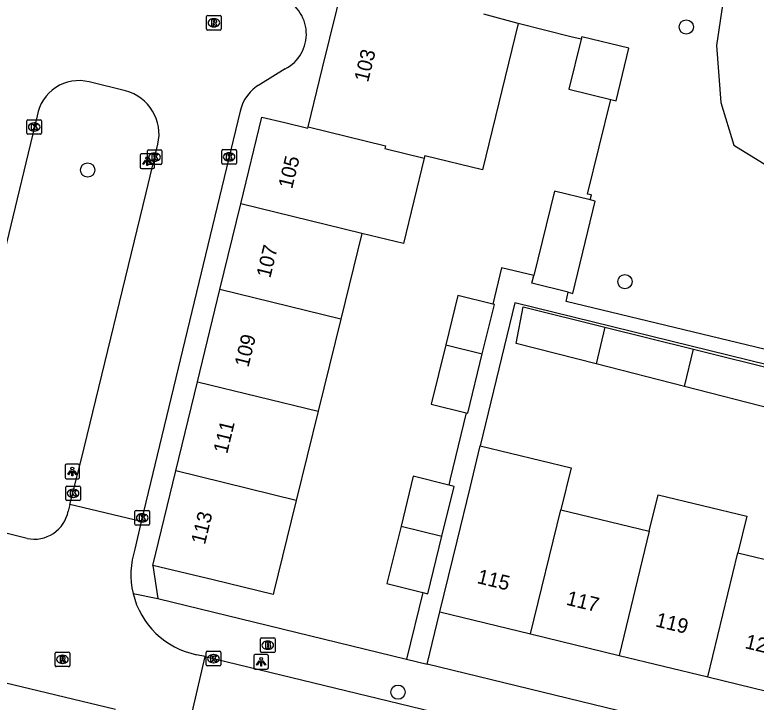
# Model space of a CAD drawing. Extents: x 162812 to 163818, y 381639 to 382470.
# Drawn here: x 163426.1 to 163477, y 382298.5 to 382345.6 of the extents above; entities that cross this region are included whole.
import ezdxf

# ---------------------------------------------------------------- set-up
doc = ezdxf.new("R2010")
doc.units = 0
for name, color, linetype in [('IMGEO_Boom', 7, 'Continuous'), ('IMGEO_Brandkraan', 7, 'Continuous'), ('IMGEO_Kolk', 7, 'Continuous'), ('IMGEO_Lichtpunt', 7, 'Continuous'), ('IMGEO_Loofbos', 7, 'Continuous'), ('IMGEO_Pand', 7, 'Continuous'), ('IMGEO_Pand_nummerreeks', 7, 'Continuous'), ('IMGEO_Rijbaan_lokaal_open', 7, 'Continuous'), ('IMGEO_Rioolput', 7, 'Continuous'), ('IMGEO_Voetpad_open', 7, 'Continuous')]:
    doc.layers.add(name, color=color, linetype=linetype)

msp = doc.modelspace()

# ---------------------------------------------------------------- linework, layer by layer
at = {"layer": 'IMGEO_Boom'}
for centre in [(163472.217, 382344.801), (163431.118, 382334.985), (163468.006, 382327.325), (163452.428, 382299.152)]:
    msp.add_circle(centre, 0.489, dxfattribs=at)
at = {"layer": 'IMGEO_Brandkraan'}
for p, q in [((163442.983, 382301.951), (163442.983, 382302.803)), ((163443.058, 382302.877), (163443.91, 382302.877)), ((163443.471, 382302.657), (163443.496, 382302.657)), ((163443.984, 382302.803), (163443.984, 382301.951)), ((163443.91, 382301.877), (163443.058, 382301.877)), ((163443.494, 382302.097), (163443.469, 382302.097))]:
    msp.add_line(p, q, dxfattribs=at)
for points in [[(163442.983, 382301.951), (163442.983, 382302.803)], [(163443.058, 382302.877), (163443.91, 382302.877)], [(163443.331, 382302.577), (163443.331, 382302.177), (163443.544, 382302.177)], [(163443.562, 382302.577), (163443.331, 382302.577)], [(163443.51, 382302.496), (163443.456, 382302.496), (163443.456, 382302.42)], [(163443.456, 382302.42), (163443.509, 382302.42)], [(163443.984, 382302.803), (163443.984, 382301.951)], [(163443.91, 382301.877), (163443.058, 382301.877)], [(163443.518, 382302.344), (163443.456, 382302.344), (163443.456, 382302.263)], [(163443.456, 382302.263), (163443.518, 382302.263)]]:
    msp.add_lwpolyline(points, dxfattribs=at)
for centre, radius, start, end in [((163443.06, 382302.801), 0.0765, 91.552, 178.448), ((163443.06, 382302.801), 0.0765, 91.552, 178.448), ((163443.511, 382302.458), 0.0379, 267.8285, 90.9355), ((163443.566, 382302.432), 0.145, 59.4692, 91.5367), ((163443.591, 382302.479), 0.0922, 285.5137, 58.1501), ((163443.596, 382302.287), 0.105, 301.3115, 78.989), ((163443.908, 382302.801), 0.0765, 1.552, 88.448), ((163443.908, 382302.801), 0.0765, 1.552, 88.448), ((163443.06, 382301.953), 0.0765, 181.552, 268.448), ((163443.06, 382301.953), 0.0765, 181.552, 268.448), ((163443.519, 382302.303), 0.0404, 269.8759, 90.5077), ((163443.55, 382302.428), 0.251, 268.6676, 293.5347), ((163443.908, 382301.953), 0.0765, 271.552, 358.448), ((163443.908, 382301.953), 0.0765, 271.552, 358.448)]:
    msp.add_arc(centre, radius, start, end, dxfattribs=at)
for centre, major_axis, ratio, start_param, end_param in [((163443.47, 382302.377), (-0.387, 0.002), 0.722429, 4.712389, 7.853982), ((163443.495, 382302.377), (-0.39, 0.002), 0.717154, 1.570796, 4.712389)]:
    msp.add_ellipse(centre, major_axis=major_axis, ratio=ratio, start_param=start_param, end_param=end_param, dxfattribs=at)
at = {"layer": 'IMGEO_Kolk'}
for p, q in [((163426.948, 382337.512), (163426.948, 382338.364)), ((163427.023, 382338.438), (163427.875, 382338.438)), ((163427.436, 382338.218), (163427.461, 382338.218)), ((163427.949, 382338.364), (163427.949, 382337.512)), ((163427.459, 382337.658), (163427.434, 382337.658)), ((163427.875, 382337.438), (163427.023, 382337.438)), ((163435.217, 382335.445), (163435.217, 382336.297)), ((163435.292, 382336.371), (163436.144, 382336.371)), ((163435.705, 382336.151), (163435.73, 382336.151)), ((163436.218, 382336.297), (163436.218, 382335.445)), ((163440.329, 382335.46), (163440.329, 382336.312)), ((163440.404, 382336.386), (163441.256, 382336.386)), ((163440.817, 382336.166), (163440.842, 382336.166)), ((163441.33, 382336.312), (163441.33, 382335.46)), ((163435.728, 382335.591), (163435.703, 382335.591)), ((163440.84, 382335.606), (163440.815, 382335.606)), ((163436.144, 382335.371), (163435.292, 382335.371)), ((163441.256, 382335.386), (163440.404, 382335.386)), ((163429.621, 382312.371), (163429.621, 382313.223)), ((163429.696, 382313.297), (163430.548, 382313.297)), ((163430.109, 382313.077), (163430.134, 382313.077)), ((163430.622, 382313.223), (163430.622, 382312.371)), ((163430.548, 382312.297), (163429.696, 382312.297)), ((163430.132, 382312.517), (163430.107, 382312.517)), ((163434.369, 382310.689), (163434.369, 382311.541)), ((163434.444, 382311.615), (163435.296, 382311.615)), ((163435.37, 382311.541), (163435.37, 382310.689)), ((163434.857, 382311.395), (163434.882, 382311.395)), ((163435.296, 382310.615), (163434.444, 382310.615)), ((163434.88, 382310.835), (163434.855, 382310.835)), ((163439.253, 382301.029), (163439.253, 382301.881)), ((163439.328, 382301.955), (163440.18, 382301.955)), ((163440.254, 382301.881), (163440.254, 382301.029)), ((163439.741, 382301.735), (163439.766, 382301.735)), ((163440.18, 382300.955), (163439.328, 382300.955)), ((163439.764, 382301.175), (163439.739, 382301.175))]:
    msp.add_line(p, q, dxfattribs=at)
for points in [[(163426.948, 382337.512), (163426.948, 382338.364)], [(163427.023, 382338.438), (163427.875, 382338.438)], [(163427.269, 382338.138), (163427.392, 382338.138), (163427.392, 382337.987), (163427.522, 382338.138), (163427.686, 382338.138), (163427.54, 382337.987), (163427.693, 382337.738), (163427.541, 382337.738), (163427.456, 382337.902), (163427.392, 382337.835), (163427.392, 382337.738), (163427.269, 382337.738), (163427.269, 382338.138)], [(163427.949, 382338.364), (163427.949, 382337.512)], [(163427.875, 382337.438), (163427.023, 382337.438)], [(163435.217, 382335.445), (163435.217, 382336.297)], [(163435.292, 382336.371), (163436.144, 382336.371)], [(163435.538, 382336.071), (163435.661, 382336.071), (163435.661, 382335.92), (163435.791, 382336.071), (163435.955, 382336.071), (163435.809, 382335.92), (163435.962, 382335.671), (163435.81, 382335.671), (163435.725, 382335.835), (163435.661, 382335.768), (163435.661, 382335.671), (163435.538, 382335.671), (163435.538, 382336.071)], [(163436.218, 382336.297), (163436.218, 382335.445)], [(163440.329, 382335.46), (163440.329, 382336.312)], [(163440.404, 382336.386), (163441.256, 382336.386)], [(163440.65, 382336.086), (163440.773, 382336.086), (163440.773, 382335.935), (163440.903, 382336.086), (163441.067, 382336.086), (163440.921, 382335.935), (163441.074, 382335.686), (163440.922, 382335.686), (163440.837, 382335.85), (163440.773, 382335.783), (163440.773, 382335.686), (163440.65, 382335.686), (163440.65, 382336.086)], [(163441.33, 382336.312), (163441.33, 382335.46)], [(163436.144, 382335.371), (163435.292, 382335.371)], [(163441.256, 382335.386), (163440.404, 382335.386)], [(163429.621, 382312.371), (163429.621, 382313.223)], [(163429.696, 382313.297), (163430.548, 382313.297)], [(163430.622, 382313.223), (163430.622, 382312.371)], [(163429.942, 382312.997), (163430.065, 382312.997), (163430.065, 382312.846), (163430.195, 382312.997), (163430.359, 382312.997), (163430.213, 382312.846), (163430.366, 382312.597), (163430.214, 382312.597), (163430.129, 382312.761), (163430.065, 382312.694), (163430.065, 382312.597), (163429.942, 382312.597), (163429.942, 382312.997)], [(163430.548, 382312.297), (163429.696, 382312.297)], [(163434.369, 382310.689), (163434.369, 382311.541)], [(163434.444, 382311.615), (163435.296, 382311.615)], [(163435.37, 382311.541), (163435.37, 382310.689)], [(163434.69, 382311.315), (163434.813, 382311.315), (163434.813, 382311.164), (163434.943, 382311.315), (163435.107, 382311.315), (163434.961, 382311.164), (163435.114, 382310.915), (163434.962, 382310.915), (163434.877, 382311.079), (163434.813, 382311.012), (163434.813, 382310.915), (163434.69, 382310.915), (163434.69, 382311.315)], [(163435.296, 382310.615), (163434.444, 382310.615)], [(163439.253, 382301.029), (163439.253, 382301.881)], [(163439.328, 382301.955), (163440.18, 382301.955)], [(163440.254, 382301.881), (163440.254, 382301.029)], [(163439.574, 382301.655), (163439.697, 382301.655), (163439.697, 382301.504), (163439.827, 382301.655), (163439.991, 382301.655), (163439.845, 382301.504), (163439.998, 382301.255), (163439.846, 382301.255), (163439.761, 382301.419), (163439.697, 382301.352), (163439.697, 382301.255), (163439.574, 382301.255), (163439.574, 382301.655)], [(163440.18, 382300.955), (163439.328, 382300.955)]]:
    msp.add_lwpolyline(points, dxfattribs=at)
for centre, start, end in [((163427.025, 382338.362), 91.552, 178.448), ((163427.025, 382338.362), 91.552, 178.448), ((163427.873, 382338.362), 1.552, 88.448), ((163427.873, 382338.362), 1.552, 88.448), ((163427.025, 382337.514), 181.552, 268.448), ((163427.025, 382337.514), 181.552, 268.448), ((163427.873, 382337.514), 271.552, 358.448), ((163427.873, 382337.514), 271.552, 358.448), ((163435.294, 382336.295), 91.552, 178.448), ((163435.294, 382336.295), 91.552, 178.448), ((163436.142, 382336.295), 1.552, 88.448), ((163436.142, 382336.295), 1.552, 88.448), ((163440.406, 382336.31), 91.552, 178.448), ((163440.406, 382336.31), 91.552, 178.448), ((163441.254, 382336.31), 1.552, 88.448), ((163441.254, 382336.31), 1.552, 88.448), ((163440.406, 382335.462), 181.552, 268.448), ((163440.406, 382335.462), 181.552, 268.448), ((163441.254, 382335.462), 271.552, 358.448), ((163441.254, 382335.462), 271.552, 358.448), ((163435.294, 382335.447), 181.552, 268.448), ((163435.294, 382335.447), 181.552, 268.448), ((163436.142, 382335.447), 271.552, 358.448), ((163436.142, 382335.447), 271.552, 358.448), ((163429.698, 382313.221), 91.552, 178.448), ((163429.698, 382313.221), 91.552, 178.448), ((163430.546, 382313.221), 1.552, 88.448), ((163430.546, 382313.221), 1.552, 88.448), ((163429.698, 382312.373), 181.552, 268.448), ((163429.698, 382312.373), 181.552, 268.448), ((163430.546, 382312.373), 271.552, 358.448), ((163430.546, 382312.373), 271.552, 358.448), ((163434.446, 382311.539), 91.552, 178.448), ((163434.446, 382311.539), 91.552, 178.448), ((163435.294, 382311.539), 1.552, 88.448), ((163435.294, 382311.539), 1.552, 88.448), ((163434.446, 382310.691), 181.552, 268.448), ((163434.446, 382310.691), 181.552, 268.448), ((163435.294, 382310.691), 271.552, 358.448), ((163435.294, 382310.691), 271.552, 358.448), ((163439.33, 382301.879), 91.552, 178.448), ((163439.33, 382301.879), 91.552, 178.448), ((163440.178, 382301.879), 1.552, 88.448), ((163440.178, 382301.879), 1.552, 88.448), ((163439.33, 382301.031), 181.552, 268.448), ((163439.33, 382301.031), 181.552, 268.448), ((163440.178, 382301.031), 271.552, 358.448), ((163440.178, 382301.031), 271.552, 358.448)]:
    msp.add_arc(centre, 0.0765, start, end, dxfattribs=at)
for centre, major_axis, ratio, start_param, end_param in [((163427.435, 382337.938), (-0.387, 0.002), 0.722429, 4.712389, 7.853982), ((163427.46, 382337.938), (-0.39, 0.002), 0.717154, 1.570796, 4.712389), ((163435.704, 382335.871), (-0.387, 0.002), 0.722429, 4.712389, 7.853982), ((163435.729, 382335.871), (-0.39, 0.002), 0.717154, 1.570796, 4.712389), ((163440.816, 382335.886), (-0.387, 0.002), 0.722429, 4.712389, 7.853982), ((163440.841, 382335.886), (-0.39, 0.002), 0.717154, 1.570796, 4.712389), ((163430.108, 382312.797), (-0.387, 0.002), 0.722429, 4.712389, 7.853982), ((163430.133, 382312.797), (-0.39, 0.002), 0.717154, 1.570796, 4.712389), ((163434.856, 382311.115), (-0.387, 0.002), 0.722429, 4.712389, 7.853982), ((163434.881, 382311.115), (-0.39, 0.002), 0.717154, 1.570796, 4.712389), ((163439.74, 382301.455), (-0.387, 0.002), 0.722429, 4.712389, 7.853982), ((163439.765, 382301.455), (-0.39, 0.002), 0.717154, 1.570796, 4.712389)]:
    msp.add_ellipse(centre, major_axis=major_axis, ratio=ratio, start_param=start_param, end_param=end_param, dxfattribs=at)
at = {"layer": 'IMGEO_Lichtpunt'}
for p, q in [((163434.715, 382335.995), (163434.715, 382335.188)), ((163434.715, 382335.995), (163434.715, 382335.188)), ((163435.617, 382336.09), (163434.809, 382336.09)), ((163435.617, 382336.09), (163434.809, 382336.09)), ((163435.711, 382335.188), (163435.711, 382335.995)), ((163435.711, 382335.188), (163435.711, 382335.995)), ((163434.809, 382335.094), (163435.617, 382335.094)), ((163434.809, 382335.094), (163435.617, 382335.094)), ((163429.568, 382314.702), (163429.568, 382313.895)), ((163429.568, 382314.702), (163429.568, 382313.895)), ((163430.47, 382314.797), (163429.662, 382314.797)), ((163430.47, 382314.797), (163429.662, 382314.797)), ((163430.564, 382313.895), (163430.564, 382314.702)), ((163430.564, 382313.895), (163430.564, 382314.702)), ((163429.662, 382313.801), (163430.47, 382313.801)), ((163429.662, 382313.801), (163430.47, 382313.801)), ((163442.53, 382301.635), (163442.53, 382300.828)), ((163442.53, 382301.635), (163442.53, 382300.828)), ((163443.432, 382301.73), (163442.624, 382301.73)), ((163443.432, 382301.73), (163442.624, 382301.73)), ((163443.526, 382300.828), (163443.526, 382301.635)), ((163443.526, 382300.828), (163443.526, 382301.635)), ((163442.624, 382300.734), (163443.432, 382300.734)), ((163442.624, 382300.734), (163443.432, 382300.734))]:
    msp.add_line(p, q, dxfattribs=at)
for points in [[(163435.089, 382335.659), (163435.128, 382335.631), (163434.94, 382335.369), (163434.902, 382335.396), (163435.089, 382335.659)], [(163435.191, 382335.611), (163435.238, 382335.611), (163435.238, 382335.289), (163435.191, 382335.289), (163435.191, 382335.611)], [(163435.301, 382335.631), (163435.339, 382335.658), (163435.526, 382335.396), (163435.487, 382335.368), (163435.301, 382335.631)], [(163429.942, 382314.366), (163429.981, 382314.338), (163429.793, 382314.076), (163429.755, 382314.103), (163429.942, 382314.366)], [(163430.044, 382314.318), (163430.091, 382314.318), (163430.091, 382313.996), (163430.044, 382313.996), (163430.044, 382314.318)], [(163430.154, 382314.338), (163430.192, 382314.365), (163430.379, 382314.103), (163430.34, 382314.075), (163430.154, 382314.338)], [(163442.904, 382301.299), (163442.943, 382301.271), (163442.755, 382301.009), (163442.717, 382301.036), (163442.904, 382301.299)], [(163443.006, 382301.251), (163443.053, 382301.251), (163443.053, 382300.929), (163443.006, 382300.929), (163443.006, 382301.251)], [(163443.116, 382301.271), (163443.154, 382301.298), (163443.341, 382301.036), (163443.302, 382301.008), (163443.116, 382301.271)]]:
    msp.add_lwpolyline(points, dxfattribs=at)
for centre in [(163435.214, 382335.793), (163430.067, 382314.5), (163443.029, 382301.433)]:
    msp.add_circle(centre, 0.0994, dxfattribs=at)
for centre, start, end in [((163434.809, 382335.995), 90, 180), ((163434.809, 382335.995), 90, 180), ((163435.617, 382335.995), 0, 90), ((163435.617, 382335.995), 0, 90), ((163434.809, 382335.188), 180, 270), ((163434.809, 382335.188), 180, 270), ((163435.617, 382335.188), 270, 0), ((163435.617, 382335.188), 270, 360), ((163429.662, 382314.702), 90, 180), ((163429.662, 382314.702), 90, 180), ((163430.47, 382314.702), 0, 90), ((163430.47, 382314.702), 0, 90), ((163429.662, 382313.895), 180, 270), ((163429.662, 382313.895), 180, 270), ((163430.47, 382313.895), 270, 0), ((163430.47, 382313.895), 270, 360), ((163442.624, 382301.635), 90, 180), ((163442.624, 382301.635), 90, 180), ((163443.432, 382301.635), 0, 90), ((163443.432, 382301.635), 0, 90), ((163442.624, 382300.828), 180, 270), ((163442.624, 382300.828), 180, 270), ((163443.432, 382300.828), 270, 0), ((163443.432, 382300.828), 270, 360)]:
    msp.add_arc(centre, 0.0946, start, end, dxfattribs=at)
at = {"layer": 'IMGEO_Loofbos'}
for points in [[(163475.535, 382351.851), (163474.295, 382343.542), (163474.58, 382339.625), (163475.478, 382336.687), (163478.334, 382334.932), (163483.843, 382334.034), (163485.639, 382335.544), (163487.434, 382341.583), (163488.536, 382345.705), (163488.702, 382348.691)], [(163464.994, 382343.956), (163464.3, 382344.13), (163460.684, 382345.036)], [(163465.624, 382332.932), (163465.709, 382333.288), (163465.442, 382333.339), (163467.037, 382339.823)]]:
    msp.add_lwpolyline(points, dxfattribs=at)
at = {"layer": 'IMGEO_Pand'}
for points in [[(163446.253, 382337.951), (163447.246, 382342.001), (163448.726, 382348.034)], [(163460.684, 382345.036), (163458.323, 382345.68)], [(163460.684, 382345.036), (163458.22, 382334.988), (163454.27, 382335.957), (163454.232, 382335.802)], [(163467.037, 382339.823), (163467.398, 382339.734), (163468.282, 382343.337), (163465.037, 382344.133), (163464.994, 382343.956)], [(163464.994, 382343.956), (163464.153, 382340.53), (163467.037, 382339.823)], [(163441.631, 382332.671), (163443.075, 382338.62), (163444.653, 382338.241), (163446.232, 382337.862), (163446.253, 382337.951)], [(163446.253, 382337.951), (163451.569, 382336.642), (163451.526, 382336.468), (163454.232, 382335.802)], [(163454.232, 382335.802), (163452.793, 382329.934), (163449.938, 382330.635)], [(163465.624, 382332.932), (163463.162, 382333.536), (163461.741, 382327.74)], [(163464.117, 382326.596), (163464.419, 382326.522), (163465.969, 382332.848), (163465.624, 382332.932)], [(163440.201, 382326.785), (163441.631, 382332.671)], [(163449.938, 382330.635), (163441.631, 382332.671)], [(163449.938, 382330.635), (163448.496, 382324.752)], [(163464.117, 382326.596), (163461.611, 382327.21), (163461.741, 382327.74)], [(163438.665, 382320.456), (163440.201, 382326.785)], [(163448.496, 382324.752), (163440.201, 382326.785)], [(163458.925, 382325.787), (163456.534, 382326.374), (163455.703, 382322.986)], [(163458.212, 382322.37), (163459.043, 382325.758), (163458.925, 382325.787)], [(163466.024, 382321.676), (163460.531, 382323.08), (163461.016, 382325.599), (163466.636, 382324.2)], [(163448.496, 382324.752), (163446.944, 382318.426)], [(163466.636, 382324.2), (163466.024, 382321.676)], [(163466.636, 382324.2), (163472.71, 382322.689)], [(163455.703, 382322.986), (163454.704, 382318.917), (163457.115, 382318.326)], [(163455.703, 382322.986), (163458.212, 382322.37)], [(163457.115, 382318.326), (163457.214, 382318.302), (163458.212, 382322.37)], [(163472.088, 382320.127), (163472.71, 382322.689)], [(163472.71, 382322.689), (163478.785, 382321.176)], [(163472.088, 382320.127), (163466.024, 382321.676)], [(163437.178, 382314.335), (163438.665, 382320.456)], [(163438.665, 382320.456), (163446.944, 382318.426)], [(163478.154, 382318.577), (163472.088, 382320.127)], [(163446.944, 382318.426), (163445.444, 382312.309)], [(163455.301, 382304.659), (163456.48, 382309.518), (163457.369, 382313.18), (163458.068, 382316.059)], [(163458.068, 382316.059), (163464.307, 382314.545), (163463.595, 382311.669)], [(163435.603, 382307.849), (163437.178, 382314.335)], [(163445.444, 382312.309), (163437.178, 382314.335)], [(163455.911, 382313.366), (163453.464, 382313.967), (163452.634, 382310.547)], [(163455.438, 382309.86), (163456.276, 382313.277), (163455.911, 382313.366)], [(163469.677, 382310.193), (163470.286, 382312.703), (163476.37, 382311.226), (163475.761, 382308.716)], [(163445.444, 382312.309), (163445.102, 382310.914), (163443.91, 382306.056), (163443.864, 382305.864), (163439.734, 382306.857), (163435.603, 382307.849)], [(163461.527, 382303.148), (163463.595, 382311.669)], [(163463.595, 382311.669), (163469.677, 382310.193)], [(163452.634, 382310.547), (163451.657, 382306.6), (163454.123, 382305.995)], [(163452.634, 382310.547), (163455.438, 382309.86)], [(163469.677, 382310.193), (163467.609, 382301.672)], [(163454.123, 382305.995), (163454.47, 382305.91), (163455.438, 382309.86)], [(163473.693, 382300.196), (163475.761, 382308.716)], [(163475.761, 382308.716), (163481.842, 382307.24)], [(163455.301, 382304.659), (163461.527, 382303.148)], [(163461.527, 382303.148), (163467.609, 382301.672)], [(163467.609, 382301.672), (163473.693, 382300.196)], [(163473.693, 382300.196), (163479.774, 382298.72)]]:
    msp.add_lwpolyline(points, dxfattribs=at)
at = {"layer": 'IMGEO_Rijbaan_lokaal_open'}
for points in [[(163444.676, 382341.92), (163442.976, 382340.871)], [(163433.721, 382340.414), (163431.213, 382341.038)], [(163441.596, 382339.022), (163434.795, 382310.869)], [(163427.647, 382338.711), (163426.87, 382335.489), (163422.441, 382317.129), (163421.662, 382313.876)], [(163429.903, 382312.042), (163430.677, 382315.065), (163435.125, 382333.412), (163435.938, 382336.75)], [(163429.903, 382312.042), (163429.788, 382311.585)], [(163434.795, 382310.869), (163429.903, 382312.042)], [(163426.96, 382309.702), (163423.075, 382310.651)], [(163434.795, 382310.869), (163434.367, 382308.975)], [(163438.06, 382296.783), (163439.177, 382301.597)], [(163439.177, 382301.597), (163438.601, 382301.725)], [(163439.177, 382301.597), (163516.445, 382282.889), (163518.999, 382282.304), (163520.643, 382281.927)], [(163420.711, 382300.926), (163433.031, 382297.984)]]:
    msp.add_lwpolyline(points, dxfattribs=at)
for centre, radius, start, end in [((163443.449, 382344.31), 2.687, 297.1773, 69.5173), ((163430.521, 382338.203), 2.918, 76.2787, 169.9743), ((163444.302, 382338.442), 2.767, 118.6286, 167.8998), ((163432.962, 382337.452), 3.058, 346.7279, 75.6264), ((163427.446, 382312.038), 2.386, 258.2516, 349.063), ((163439.687, 382307.223), 5.601, 161.7743, 193.3787), ((163439.69, 382307.222), 5.603, 193.3587, 258.7951)]:
    msp.add_arc(centre, radius, start, end, dxfattribs=at)
at = {"layer": 'IMGEO_Rioolput'}
for p, q in [((163439.287, 382344.664), (163439.287, 382345.516)), ((163439.362, 382345.59), (163440.214, 382345.59)), ((163439.775, 382345.37), (163439.8, 382345.37)), ((163440.288, 382345.516), (163440.288, 382344.664)), ((163439.798, 382344.81), (163439.773, 382344.81)), ((163440.214, 382344.59), (163439.362, 382344.59)), ((163428.962, 382301.903), (163429.814, 382301.903)), ((163428.887, 382300.977), (163428.887, 382301.829)), ((163429.375, 382301.683), (163429.4, 382301.683)), ((163429.888, 382301.829), (163429.888, 382300.977)), ((163429.814, 382300.903), (163428.962, 382300.903)), ((163429.398, 382301.123), (163429.373, 382301.123))]:
    msp.add_line(p, q, dxfattribs=at)
for points in [[(163439.287, 382344.664), (163439.287, 382345.516)], [(163439.362, 382345.59), (163440.214, 382345.59)], [(163439.876, 382345.288), (163439.624, 382345.29), (163439.624, 382344.89)], [(163439.802, 382345.209), (163439.748, 382345.209), (163439.748, 382345.128)], [(163439.748, 382345.128), (163439.8, 382345.128)], [(163440.288, 382345.516), (163440.288, 382344.664)], [(163439.624, 382344.89), (163439.748, 382344.89), (163439.748, 382345.052), (163439.759, 382345.052)], [(163439.806, 382345.023), (163439.877, 382344.89), (163440.017, 382344.89), (163439.952, 382345.016)], [(163440.214, 382344.59), (163439.362, 382344.59)], [(163428.962, 382301.903), (163429.814, 382301.903)], [(163428.887, 382300.977), (163428.887, 382301.829)], [(163429.476, 382301.601), (163429.224, 382301.603), (163429.224, 382301.203)], [(163429.224, 382301.203), (163429.348, 382301.203), (163429.348, 382301.365), (163429.359, 382301.365)], [(163429.402, 382301.522), (163429.348, 382301.522), (163429.348, 382301.441)], [(163429.348, 382301.441), (163429.4, 382301.441)], [(163429.888, 382301.829), (163429.888, 382300.977)], [(163429.814, 382300.903), (163428.962, 382300.903)], [(163429.406, 382301.336), (163429.477, 382301.203), (163429.617, 382301.203), (163429.552, 382301.329)]]:
    msp.add_lwpolyline(points, dxfattribs=at)
for centre, radius, start, end in [((163439.364, 382345.514), 0.0765, 91.552, 178.448), ((163439.364, 382345.514), 0.0765, 91.552, 178.448), ((163439.784, 382345.317), 0.19, 274.7715, 282.9687), ((163439.808, 382345.113), 0.0964, 77.0061, 93.1865), ((163439.822, 382345.17), 0.0378, 276.6634, 79.6772), ((163439.875, 382345.178), 0.109, 350.3612, 89.416), ((163439.873, 382345.178), 0.112, 277.5842, 350.9817), ((163440.212, 382345.514), 0.0765, 1.552, 88.448), ((163440.212, 382345.514), 0.0765, 1.552, 88.448), ((163439.364, 382344.666), 0.0765, 181.552, 268.448), ((163439.364, 382344.666), 0.0765, 181.552, 268.448), ((163439.758, 382344.999), 0.0533, 26.0293, 88.6989), ((163439.857, 382344.963), 0.108, 29.5134, 73.7905), ((163440.212, 382344.666), 0.0765, 271.552, 358.448), ((163440.212, 382344.666), 0.0765, 271.552, 358.448), ((163428.964, 382301.827), 0.0765, 91.552, 178.448), ((163428.964, 382301.827), 0.0765, 91.552, 178.448), ((163429.812, 382301.827), 0.0765, 1.552, 88.448), ((163429.812, 382301.827), 0.0765, 1.552, 88.448), ((163429.358, 382301.312), 0.0533, 26.0293, 88.6989), ((163429.384, 382301.63), 0.19, 274.7715, 282.9687), ((163429.408, 382301.426), 0.0964, 77.0061, 93.1865), ((163429.422, 382301.483), 0.0378, 276.6634, 79.6772), ((163429.475, 382301.491), 0.109, 350.3612, 89.416), ((163429.473, 382301.491), 0.112, 277.5842, 350.9817), ((163429.457, 382301.276), 0.108, 29.5134, 73.7905), ((163428.964, 382300.979), 0.0765, 181.552, 268.448), ((163428.964, 382300.979), 0.0765, 181.552, 268.448), ((163429.812, 382300.979), 0.0765, 271.552, 358.448), ((163429.812, 382300.979), 0.0765, 271.552, 358.448)]:
    msp.add_arc(centre, radius, start, end, dxfattribs=at)
for centre, major_axis, ratio, start_param, end_param in [((163439.774, 382345.09), (-0.387, 0.002), 0.722429, 4.712389, 7.853982), ((163439.799, 382345.09), (-0.39, 0.002), 0.717154, 1.570796, 4.712389), ((163429.374, 382301.403), (-0.387, 0.002), 0.722429, 4.712389, 7.853982), ((163429.399, 382301.403), (-0.39, 0.002), 0.717154, 1.570796, 4.712389)]:
    msp.add_ellipse(centre, major_axis=major_axis, ratio=ratio, start_param=start_param, end_param=end_param, dxfattribs=at)
at = {"layer": 'IMGEO_Voetpad_open'}
for points in [[(163461.741, 382327.74), (163459.53, 382328.282), (163458.925, 382325.787)], [(163503.731, 382317.543), (163503.479, 382316.463), (163500.541, 382317.17), (163500, 382317.3), (163463.969, 382325.973), (163464.117, 382326.596)], [(163501.074, 382306.27), (163503.294, 382315.351), (163460.453, 382325.878), (163458.068, 382316.059)], [(163457.115, 382318.326), (163456.015, 382313.794), (163455.911, 382313.366)], [(163435.603, 382307.849), (163435.933, 382305.574)], [(163454.123, 382305.995), (163453.011, 382301.415)], [(163434.238, 382305.927), (163435.933, 382305.574)], [(163435.933, 382305.574), (163453.011, 382301.415)], [(163454.429, 382301.07), (163455.301, 382304.659)], [(163453.011, 382301.415), (163454.429, 382301.07)], [(163497.29, 382290.634), (163454.429, 382301.07)]]:
    msp.add_lwpolyline(points, dxfattribs=at)

# ---------------------------------------------------------------- texts
at = {"layer": 'IMGEO_Pand_nummerreeks'}
for s, rotation, p in [('103', 76.2194, (163450.369, 382340.961)), ('105', 76.2193, (163445.155, 382333.648)), ('107', 76.2193, (163443.653, 382327.523)), ('109', 76.2193, (163442.151, 382321.397)), ('111', 76.2193, (163440.696, 382315.471)), ('113', 76.2193, (163439.168, 382309.235)), ('115', 346.3594, (163457.796, 382306.647)), ('117', 346.3594, (163463.92, 382305.161)), ('119', 346.3579, (163470.044, 382303.675)), ('121', 346.3594, (163476.189, 382302.183))]:
    msp.add_text(s, height=1, rotation=rotation, dxfattribs=at).set_placement(p)

doc.saveas('drawing.dxf')
